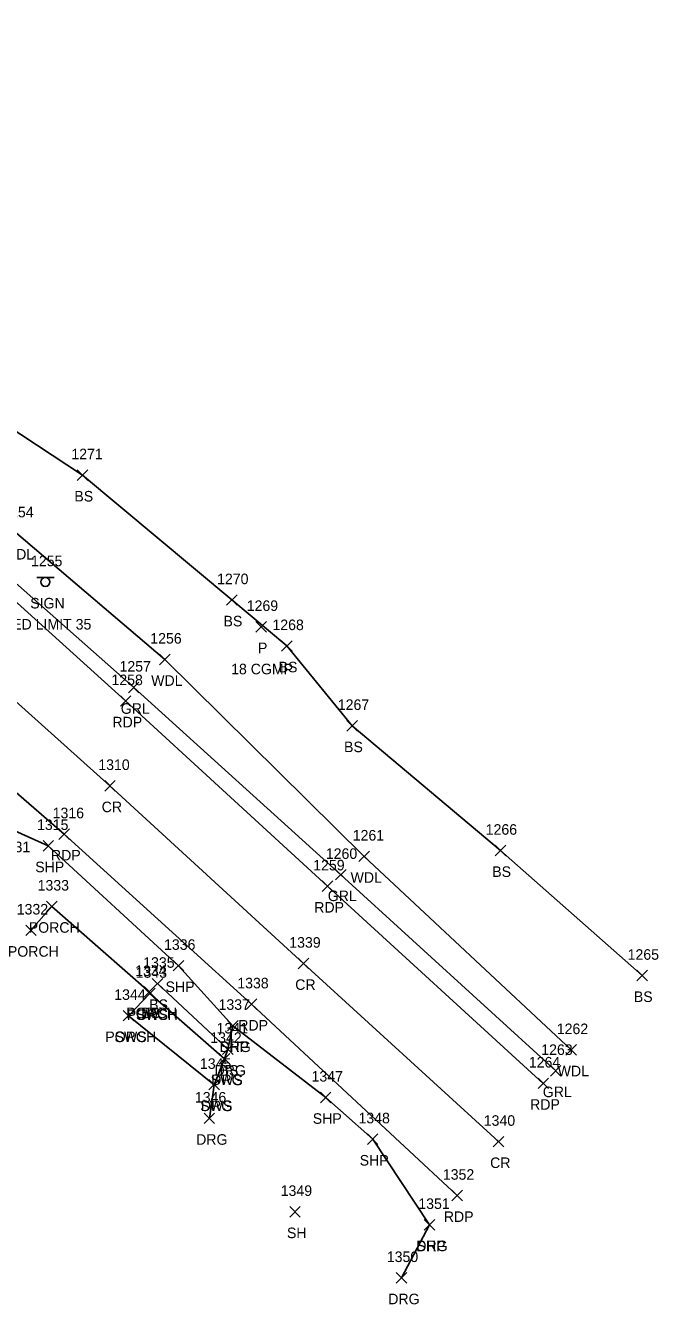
# Model space of a CAD drawing. Extents: x 1647133 to 1649138, y 411736 to 414924.
# Drawn here: x 1648935.4 to 1649055.4, y 411735.8 to 411978.2 of the extents above; entities that cross this region are included whole.
import ezdxf

# ---------------------------------------------------------------- set-up
doc = ezdxf.new("R2010")
doc.units = 0
for name, color, linetype in [('D_A', 7, 'Continuous'), ('D_C', 7, 'Continuous'), ('D_I', 7, 'Continuous'), ('D_TIC', 7, 'Continuous'), ('L_A', 7, 'Continuous'), ('L_I', 7, 'Continuous'), ('L_TIC', 7, 'Continuous'), ('LAWA', 7, 'Continuous'), ('LBF', 7, 'Continuous'), ('LELB', 7, 'Continuous'), ('P_A', 7, 'Continuous'), ('P_I', 7, 'Continuous'), ('P_TIC', 7, 'Continuous'), ('PET', 7, 'Continuous'), ('PRC', 7, 'Continuous'), ('PSP', 7, 'Continuous'), ('R_A', 7, 'Continuous'), ('R_I', 7, 'Continuous'), ('R_TIC', 7, 'Continuous'), ('RDG', 7, 'Continuous'), ('RGR', 7, 'Continuous'), ('RSW', 7, 'Continuous'), ('S_A', 7, 'Continuous'), ('S_C', 7, 'Continuous'), ('S_I', 7, 'Continuous'), ('SSGN', 7, 'Continuous')]:
    doc.layers.add(name, color=color, linetype=linetype)

msp = doc.modelspace()

# ---------------------------------------------------------------- linework, layer by layer
at = {"layer": 'D_TIC'}
for points in [[(1648979.09, 411863.24), (1648981.09, 411865.24)], [(1648981.09, 411863.24), (1648979.09, 411865.24)]]:
    msp.add_lwpolyline(points, dxfattribs=at)
at = {"layer": 'L_TIC'}
for points in [[(1648945.23, 411891.99), (1648947.23, 411893.99)], [(1648947.23, 411891.99), (1648945.23, 411893.99)], [(1648973.5, 411868.32), (1648975.5, 411870.32)], [(1648975.5, 411868.32), (1648973.5, 411870.32)], [(1648983.95, 411859.61), (1648985.95, 411861.61)], [(1648985.95, 411859.61), (1648983.95, 411861.61)], [(1648960.81, 411857.05), (1648962.81, 411859.05)], [(1648962.81, 411857.05), (1648960.81, 411859.05)], [(1648996.34, 411844.48), (1648998.34, 411846.48)], [(1648998.34, 411844.48), (1648996.34, 411846.48)], [(1648998.6, 411819.73), (1649000.6, 411821.73)], [(1649000.6, 411819.73), (1648998.6, 411821.73)], [(1649024.42, 411820.83), (1649026.42, 411822.83)], [(1649026.42, 411820.83), (1649024.42, 411822.83)], [(1648939.41, 411810.25), (1648941.41, 411812.25)], [(1648941.41, 411810.25), (1648939.41, 411812.25)], [(1648935.45, 411805.71), (1648937.45, 411807.71)], [(1648937.45, 411805.71), (1648935.45, 411807.71)], [(1649051.27, 411797.13), (1649053.27, 411799.13)], [(1649053.27, 411797.13), (1649051.27, 411799.13)], [(1648959.41, 411795.61), (1648961.41, 411797.61)], [(1648961.41, 411795.61), (1648959.41, 411797.61)], [(1648957.88, 411794.05), (1648959.88, 411796.05)], [(1648959.88, 411794.05), (1648957.88, 411796.05)], [(1648957.88, 411794.05), (1648959.88, 411796.05)], [(1648959.88, 411794.05), (1648957.88, 411796.05)], [(1648957.98, 411793.72), (1648959.98, 411795.72)], [(1648959.98, 411793.72), (1648957.98, 411795.72)], [(1648953.92, 411789.53), (1648955.92, 411791.53)], [(1648955.92, 411789.53), (1648953.92, 411791.53)], [(1648972.75, 411783.16), (1648974.75, 411785.16)], [(1648974.75, 411783.16), (1648972.75, 411785.16)], [(1649037.84, 411783.04), (1649039.84, 411785.04)], [(1649039.84, 411783.04), (1649037.84, 411785.04)], [(1648985.48, 411752.37), (1648987.48, 411754.37)], [(1648987.48, 411752.37), (1648985.48, 411754.37)]]:
    msp.add_lwpolyline(points, dxfattribs=at)
at = {"layer": 'LAWA'}
msp.add_lwpolyline([(1648868.17, 411960.17), (1648864.04, 411954.98), (1648884.1, 411929.27), (1648898.93, 411912.58), (1648933.69, 411881.99), (1648961.81, 411858.05), (1648999.6, 411820.73), (1649038.84, 411784.04)], dxfattribs=at)
at = {"layer": 'LBF'}
msp.add_lwpolyline([(1648936.45, 411806.71), (1648940.41, 411811.25), (1648958.88, 411795.05), (1648958.98, 411794.72), (1648954.92, 411790.53)], dxfattribs=at)
at = {"layer": 'LELB'}
for points in [[(1649052.27, 411798.13), (1649025.42, 411821.83), (1648997.34, 411845.48), (1648984.95, 411860.61), (1648974.5, 411869.32), (1648946.23, 411892.99), (1648925.73, 411906.44)], [(1648958.88, 411795.05), (1648960.41, 411796.61), (1648973.75, 411784.16)]]:
    msp.add_lwpolyline(points, dxfattribs=at)
at = {"layer": 'P_TIC'}
for points in [[(1648953.39, 411849.18), (1648955.39, 411851.18)], [(1648955.39, 411849.18), (1648953.39, 411851.18)], [(1648950.42, 411833.1), (1648952.42, 411835.1)], [(1648952.42, 411833.1), (1648950.42, 411835.1)], [(1648941.74, 411823.95), (1648943.74, 411825.95)], [(1648943.74, 411823.95), (1648941.74, 411825.95)], [(1648938.73, 411821.73), (1648940.73, 411823.73)], [(1648940.73, 411821.73), (1648938.73, 411823.73)], [(1648991.64, 411814.07), (1648993.64, 411816.07)], [(1648993.64, 411814.07), (1648991.64, 411816.07)], [(1648963.42, 411799.01), (1648965.42, 411801.01)], [(1648965.42, 411799.01), (1648963.42, 411801.01)], [(1648987.1, 411799.42), (1648989.1, 411801.42)], [(1648989.1, 411799.42), (1648987.1, 411801.42)], [(1648977.24, 411791.71), (1648979.24, 411793.71)], [(1648979.24, 411791.71), (1648977.24, 411793.71)], [(1648973.69, 411787.64), (1648975.69, 411789.64)], [(1648975.69, 411787.64), (1648973.69, 411789.64)], [(1649032.55, 411776.71), (1649034.55, 411778.71)], [(1649034.55, 411776.71), (1649032.55, 411778.71)], [(1648991.31, 411774.04), (1648993.31, 411776.04)], [(1648993.31, 411774.04), (1648991.31, 411776.04)], [(1649000.21, 411766.13), (1649002.21, 411768.13)], [(1649002.21, 411766.13), (1649000.21, 411768.13)], [(1649024.04, 411765.66), (1649026.04, 411767.66)], [(1649026.04, 411765.66), (1649024.04, 411767.66)], [(1649016.21, 411755.44), (1649018.21, 411757.44)], [(1649018.21, 411755.44), (1649016.21, 411757.44)], [(1649010.98, 411749.9), (1649012.98, 411751.9)], [(1649012.98, 411749.9), (1649010.98, 411751.9)]]:
    msp.add_lwpolyline(points, dxfattribs=at)
at = {"layer": 'PET'}
for points in [[(1648755.32, 411988.12), (1648772.85, 411971.96), (1648796.64, 411951.34), (1648831.69, 411920.96), (1648865.67, 411891.79), (1648882.41, 411878.08), (1648919.24, 411845.27), (1648942.74, 411824.95), (1648978.24, 411792.71), (1649017.21, 411756.44)], [(1648794.52, 411987.62), (1648826.41, 411959.79), (1648844.85, 411943.99), (1648873.22, 411921.13), (1648895.79, 411903), (1648925.88, 411875.91), (1648954.39, 411850.18), (1648992.64, 411815.07), (1649033.55, 411777.71)]]:
    msp.add_lwpolyline(points, dxfattribs=at)
at = {"layer": 'PRC'}
msp.add_lwpolyline([(1648523.86, 412428.16), (1648541.76, 412388.82), (1648560.79, 412347.22), (1648578.95, 412307.66), (1648596.52, 412268.85), (1648615.51, 412228.06), (1648629.38, 412198.52), (1648645.41, 412164.54), (1648659.58, 412134.14), (1648672.04, 412110.75), (1648683.9, 412091.11), (1648700.38, 412068.34), (1648715.84, 412049.98), (1648739.6, 412024.91), (1648761.87, 412004.35), (1648787.64, 411981.06), (1648820.99, 411950.62), (1648837.38, 411936.25), (1648865.13, 411910.89), (1648893.84, 411885.62), (1648930.35, 411852.9), (1648951.42, 411834.1), (1648988.1, 411800.42), (1649025.04, 411766.66)], dxfattribs=at)
at = {"layer": 'PSP'}
msp.add_lwpolyline([(1648931.15, 411834.96), (1648928.8, 411831.24), (1648926.91, 411829.26), (1648927.73, 411828.08), (1648939.73, 411822.73), (1648964.42, 411800.01), (1648974.69, 411788.64), (1648992.31, 411775.04), (1649001.21, 411767.13), (1649011.98, 411750.9)], dxfattribs=at)
at = {"layer": 'R_TIC'}
for points in [[(1648954.92, 411851.75), (1648956.92, 411853.75)], [(1648956.92, 411851.75), (1648954.92, 411853.75)], [(1648994.16, 411816.25), (1648996.16, 411818.25)], [(1648996.16, 411816.25), (1648994.16, 411818.25)], [(1648957.98, 411793.72), (1648959.98, 411795.72)], [(1648959.98, 411793.72), (1648957.98, 411795.72)], [(1648953.92, 411789.53), (1648955.92, 411791.53)], [(1648955.92, 411789.53), (1648953.92, 411791.53)], [(1648973.69, 411787.64), (1648975.69, 411789.64)], [(1648975.69, 411787.64), (1648973.69, 411789.64)], [(1648972.75, 411783.16), (1648974.75, 411785.16)], [(1648974.75, 411783.16), (1648972.75, 411785.16)], [(1648972.13, 411781.37), (1648974.13, 411783.37)], [(1648974.13, 411781.37), (1648972.13, 411783.37)], [(1648972.13, 411781.37), (1648974.13, 411783.37)], [(1648974.13, 411781.37), (1648972.13, 411783.37)], [(1649034.9, 411779.09), (1649036.9, 411781.09)], [(1649036.9, 411779.09), (1649034.9, 411781.09)], [(1648970.16, 411776.45), (1648972.16, 411778.45)], [(1648972.16, 411776.45), (1648970.16, 411778.45)], [(1648970.16, 411776.45), (1648972.16, 411778.45)], [(1648972.16, 411776.45), (1648970.16, 411778.45)], [(1648969.26, 411770.07), (1648971.26, 411772.07)], [(1648971.26, 411770.07), (1648969.26, 411772.07)], [(1649010.98, 411749.9), (1649012.98, 411751.9)], [(1649012.98, 411749.9), (1649010.98, 411751.9)], [(1649005.67, 411739.84), (1649007.67, 411741.84)], [(1649007.67, 411739.84), (1649005.67, 411741.84)]]:
    msp.add_lwpolyline(points, dxfattribs=at)
at = {"layer": 'RDG'}
for points in [[(1648974.69, 411788.64), (1648973.75, 411784.16), (1648973.13, 411782.37), (1648971.16, 411777.45), (1648970.26, 411771.07)], [(1649006.67, 411740.84), (1649011.98, 411750.9)]]:
    msp.add_lwpolyline(points, dxfattribs=at)
at = {"layer": 'RGR'}
msp.add_lwpolyline([(1648880.49, 411926.76), (1648895.83, 411907.68), (1648906.01, 411897.4), (1648927.47, 411877.9), (1648955.92, 411852.75), (1648995.16, 411817.25), (1649035.9, 411780.09)], dxfattribs=at)
at = {"layer": 'RSW'}
for points in [[(1648973.13, 411782.37), (1648958.98, 411794.72)], [(1648954.92, 411790.53), (1648971.16, 411777.45)]]:
    msp.add_lwpolyline(points, dxfattribs=at)
at = {"layer": 'SSGN'}
for p, q in [((1648937.53, 411873.57), (1648940.86, 411873.57)), ((1648939.17, 411872.74), (1648939.17, 411872.74))]:
    msp.add_line(p, q, dxfattribs=at)
msp.add_circle((1648939.17, 411872.74), 0.833, dxfattribs=at)

# ---------------------------------------------------------------- texts
at = {"layer": 'D_A'}
msp.add_text('P', height=2, dxfattribs=at).set_placement((1648979.47, 411859.24))
at = {"layer": 'D_C'}
msp.add_text('18 CGMP', height=2, dxfattribs=at).set_placement((1648974.38, 411855.24))
at = {"layer": 'D_I'}
msp.add_text('1269', height=2, dxfattribs=at).set_placement((1648977.34, 411867.24))
at = {"layer": 'L_A'}
for s, p in [('BS', (1648944.67, 411887.99)), ('WDL', (1648931.11, 411876.99)), ('BS', (1648972.94, 411864.32)), ('BS', (1648983.39, 411855.61)), ('WDL', (1648959.23, 411853.05)), ('BS', (1648995.78, 411840.48)), ('BS', (1649023.87, 411816.83)), ('WDL', (1648997.02, 411815.73)), ('PORCH', (1648936.03, 411806.25)), ('PORCH', (1648932.07, 411801.71)), ('BS', (1649050.71, 411793.13)), ('PORCH', (1648954.5, 411790.05)), ('BS', (1648957.32, 411790.05)), ('BS', (1648958.85, 411791.61)), ('PORCH', (1648954.61, 411789.72)), ('PORCH', (1648950.54, 411785.53)), ('BS', (1648972.19, 411779.16)), ('WDL', (1649036.26, 411779.04)), ('SH', (1648984.96, 411748.37))]:
    msp.add_text(s, height=2, dxfattribs=at).set_placement(p)
at = {"layer": 'L_I'}
for s, p in [('1271', (1648944.1, 411895.99)), ('1254', (1648931, 411884.99)), ('1270', (1648971.72, 411872.32)), ('1268', (1648982.21, 411863.61)), ('1256', (1648959.06, 411861.05)), ('1267', (1648994.6, 411848.48)), ('1261', (1648997.43, 411823.73)), ('1266', (1649022.63, 411824.83)), ('1331', (1648930.36, 411821.52)), ('1333', (1648937.71, 411814.25)), ('1332', (1648933.75, 411809.71)), ('1335', (1648957.72, 411799.61)), ('1265', (1649049.53, 411801.13)), ('1334', (1648956.19, 411798.05)), ('1334', (1648956.19, 411798.05)), ('1343', (1648956.29, 411797.72)), ('1344', (1648952.23, 411793.53)), ('1341', (1648971.63, 411787.16)), ('1262', (1649036.1, 411787.04)), ('1349', (1648983.78, 411756.37))]:
    msp.add_text(s, height=2, dxfattribs=at).set_placement(p)
at = {"layer": 'P_A'}
for s, p in [('RDP', (1648951.88, 411845.18)), ('CR', (1648949.85, 411829.1)), ('RDP', (1648940.23, 411819.95)), ('SHP', (1648937.26, 411817.73)), ('RDP', (1648990.13, 411810.07)), ('SHP', (1648961.96, 411795.01)), ('CR', (1648986.53, 411795.42)), ('RDP', (1648975.73, 411787.71)), ('SHP', (1648972.23, 411783.64)), ('RDP', (1649031.04, 411772.71)), ('SHP', (1648989.85, 411770.04)), ('SHP', (1648998.75, 411762.13)), ('CR', (1649023.47, 411761.66)), ('RDP', (1649014.69, 411751.44)), ('SHP', (1649009.52, 411745.9))]:
    msp.add_text(s, height=2, dxfattribs=at).set_placement(p)
at = {"layer": 'P_I'}
for s, p in [('1258', (1648951.7, 411853.18)), ('1310', (1648949.21, 411837.1)), ('1316', (1648940.56, 411827.95)), ('1315', (1648937.6, 411825.73)), ('1259', (1648989.94, 411818.07)), ('1336', (1648961.67, 411803.01)), ('1339', (1648985.4, 411803.42)), ('1338', (1648975.55, 411795.71)), ('1337', (1648972, 411791.64)), ('1264', (1649030.81, 411780.71)), ('1347', (1648989.62, 411778.04)), ('1348', (1648998.52, 411770.13)), ('1340', (1649022.26, 411769.66)), ('1352', (1649014.51, 411759.44)), ('1351', (1649009.86, 411753.9))]:
    msp.add_text(s, height=2, dxfattribs=at).set_placement(p)
at = {"layer": 'R_A'}
for s, p in [('GRL', (1648953.46, 411847.75)), ('GRL', (1648992.7, 411812.25)), ('SWS', (1648956.35, 411789.72)), ('SWS', (1648952.29, 411785.53)), ('DRG', (1648972.18, 411783.64)), ('DRG', (1648971.24, 411779.16)), ('SWS', (1648970.5, 411777.37)), ('DRG', (1648970.62, 411777.37)), ('GRL', (1649033.45, 411775.09)), ('SWS', (1648968.53, 411772.45)), ('DRG', (1648968.65, 411772.45)), ('DRG', (1648967.75, 411766.07)), ('DRG', (1649009.47, 411745.9)), ('DRG', (1649004.16, 411735.84))]:
    msp.add_text(s, height=2, dxfattribs=at).set_placement(p)
at = {"layer": 'R_I'}
for s, p in [('1257', (1648953.23, 411855.75)), ('1260', (1648992.33, 411820.25)), ('1343', (1648956.29, 411797.72)), ('1344', (1648952.23, 411793.53)), ('1337', (1648972, 411791.64)), ('1342', (1648970.44, 411785.37)), ('1342', (1648970.44, 411785.37)), ('1341', (1648971.63, 411787.16)), ('1263', (1649033.16, 411783.09)), ('1345', (1648968.47, 411780.45)), ('1345', (1648968.47, 411780.45)), ('1346', (1648967.51, 411774.07)), ('1351', (1649009.86, 411753.9)), ('1350', (1649003.89, 411743.84))]:
    msp.add_text(s, height=2, dxfattribs=at).set_placement(p)
at = {"layer": 'S_A'}
msp.add_text('SIGN', height=2, dxfattribs=at).set_placement((1648936.31, 411867.72))
at = {"layer": 'S_C'}
msp.add_text('SPEED LIMIT 35', height=2, dxfattribs=at).set_placement((1648927.53, 411863.72))
at = {"layer": 'S_I'}
msp.add_text('1255', height=2, dxfattribs=at).set_placement((1648936.46, 411875.72))

doc.saveas('drawing.dxf')
